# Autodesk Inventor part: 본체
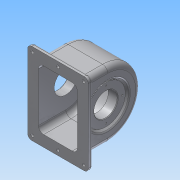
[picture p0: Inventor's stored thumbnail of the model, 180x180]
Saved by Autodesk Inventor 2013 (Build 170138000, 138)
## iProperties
Created: 2015-09
Part Number: 본체
Material: 알루미늄 6061
Document SubType Name: Modeling
Designer: user-11
Density: 2.71 g/cm^3
Mass: 756.275 g
Surface Area: 900.347 cm^2
Volume: 279.068 cm^3
Author: user-11
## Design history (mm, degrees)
sketch "스케치2"
  geometry: L1 (-52, 7)-(52, 7); L2 (52, 7)-(52, 0); L3 (52, 0)-(-52, 0); L4 (-52, 0)-(-52, 7); 1 further point
  constraints: 8 end point, 2 parallel, 1 horizontal, 1 perpendicular
  dimensions: "d0" = 7 distance from line of point (0, 0) L1; "d1" = 0 distance from line of point (0, 0) L3; "d2" = 52 distance from line of point (0, 0) L4; "d3" = 104 distance between parallel lines of L4 L2
extrude "돌출1" new body sketch "스케치2" stored distance "d4" = 140; taper "d5" = 0 deg
node "작업 평면1"
sketch "스케치3"
  geometry: L1 (0, 0)-(140, 0) reference; L2 (0, 7)-(0, 0) reference; L3 (140, 7)-(0, 7) reference; L4 (140, 0)-(140, 7) reference; L5 (70, 0)-(70, 110); L6 (70, 104)-(79.701, 104); L7 (70, 47)-(96.584, 47); L8 (13, 47)-(13, 7); L9 (127, 47)-(127, 7); A1 r 57 centre (70, 47) between (127, 47) and (13, 47)
  constraints: 10 end point, 5 point on line, 3 parallel, 3 point on circle, 2 perpendicular, 2 tangent, 1 centre point, 1 coincident
  dimensions: "d6" = 110 distance of L5.start L5.end; "d7" = 6 distance from line of L5.end L6; "d8" = 47 distance between parallel lines of L1 L7
extrude "돌출2" join sketch "스케치3" stored distance "d9" = 77; taper "d10" = 0 deg
node "작업 평면2"
sketch "스케치4"
  geometry: L1 (-127, 7)-(-127, 47) reference; L2 (-13, 47)-(-13, 7) reference; L3 (-121, 47)-(-121, 0); L4 (-19, 47)-(-19, 0); L5 (0, 0)-(-140, 0) reference; A1 r 57 centre (-70, 47) between (-13, 47) and (-127, 47) reference; A2 r 51 centre (-70, 47) between (-19, 47) and (-121, 47); 1 further point
  constraints: 4 end point, 3 parallel, 2 point on circle, 2 point on line, 1 centre point, 1 coincident, 1 tangent
  dimensions: "d11" = 51 distance from line of point (-70, 0) L3; "d12" = 102 distance between parallel lines of L3 L4
extrude "돌출3" cut sketch "스케치4" stored distance "d13" = 67; taper "d14" = 0 deg
node "작업 평면3"
sketch "스케치5"
  geometry: L1 (-38.5, 104)-(-38.5, 47) reference; L2 (-38.5, 47)-(-38.5, 7) reference; L3 (-33.5, 47)-(-33.5, 0) reference; L4 (-33.5, 98)-(-33.5, 47) reference; L5 (33.5, 47)-(33.5, 98) reference; L6 (33.5, 0)-(33.5, 47) reference; L7 (38.5, 7)-(38.5, 47) reference; L8 (38.5, 47)-(38.5, 104) reference; L9 (-49.023, 47)-(65.763, 47); L10 (-19.5, 67)-(-19.5, 75); L11 (-19.5, 75)-(-33.5, 86.747); L12 (-19.5, 67)-(-33.5, 67); L13 (48.5, 47)-(48.5, 78); L14 (48.5, 78)-(38.5, 78); L15 (48.5, 47)-(38.5, 47); 1 further point
  constraints: 14 end point, 5 perpendicular, 4 point on line
  dimensions: "d15" = 47 distance from line of point (0, 0) L9; "d16" = 40 diameter of L12 L9; "d17" = 56 diameter of L10.end L9; "d18" = 50 deg angle of L4 L11; "d19" = 10 distance between parallel lines of L8 L13; "d20" = 62 diameter of L14 L9; "d21" = 19 distance between parallel lines of L1 L10
revolve "회전1" sketch "스케치5" stored, may be unused: angle "d22" = 90 deg
sketch "스케치6"
  geometry: C1 r 31 at (0, 0) reference; C2 r 20 at (0, 0); 1 further point
  constraints: 1 centre point, 1 coincident
  dimensions: "d23" = 40 diameter of C2
extrude "돌출4" cut sketch "스케치6" stored distance "d25" = 67; taper "d26" = 0 deg
sketch "스케치7"
  geometry: L1 (-33.5, 86.747)-(-19.5, 75) reference; L2 (-33.5, 7.253)-(-19.5, 19) reference; L3 (-35.5, 80)-(-35.5, 67); L4 (-19.5, 27)-(-19.5, 67) reference; L5 (-38.5, 84.416)-(-33.237, 80); L6 (-19.5, 19)-(-19.5, 75) reference; L7 (-38.5, 104)-(-38.5, 47) reference; L8 (-38.5, 27)-(-38.5, 67) reference; L9 (-38.5, 47)-(-38.5, 7) reference; L10 (-66.176, 47)-(7.982, 47); L11 (33.5, 0)-(-33.5, 0) reference; L12 (-35.5, 80)-(-33.237, 80); L13 (-19.5, 67)-(-38.5, 67) reference; 1 further point
  constraints: 8 end point, 2 parallel, 2 point on line, 1 perpendicular, 1 vertical
  dimensions: "d27" = 16 distance between parallel lines of L4 L3; "d28" = 5 distance between parallel lines of L1 L5; "d29" = 47 distance between parallel lines of L11 L10; "d30" = 66 diameter of L3.start L10
revolve "회전2" sketch "스케치7" stored, may be unused: angle "d31" = 90 deg
sketch "스케치8"
  geometry: C1 r 20 at (0, 0) reference; C2 r 28 at (0, 0); C3 r 5.258 at (0, 28); 1 further point
  constraints: 2 centre point, 1 coincident
  dimensions: "d32" = 56 diameter of C2
hole "구멍1" sketch "스케치8" at (0, 28) diameter "d34" = 2.459; stored, may be unused: countersink angle "d38" = 90 deg, drill point angle "d40" = 118 deg; dims "d35" = 7, "d36" = 4, "d37" = 2, "d39" = 9
sketch "스케치9" dims "d44" = 48
  geometry: C1 r 31 at (0, 0) reference; C2 r 2.394 at (0, 24); 2 further points
  constraints: 1 centre point, 1 coincident, 1 vertical alignment, 2 other
hole "구멍2" sketch "스케치9" at (0, 24) diameter "d46" = 2.459; stored, may be unused: countersink angle "d50" = 90 deg, drill point angle "d52" = 118 deg; dims "d47" = 6, "d48" = 4, "d49" = 2, "d51" = 8
node "작업 평면4"
sketch "스케치10"
  geometry: L1 (0, 0)-(0, 110); L2 (38.5, 104)-(-38.5, 104) reference; L3 (-33.5, 98)-(33.5, 98) reference; L4 (0, 110)-(-6, 110); L5 (-6, 110)-(-7.886, 99.307); L6 (-7.886, 99.307)-(0, 99.307)
  constraints: 8 end point, 1 parallel, 1 perpendicular, 1 point on line, 1 vertical
  dimensions: "d62" = 110 distance of L1.start L1.end; "d63" = 12 diameter of L4.end L1; "d64" = 100 deg angle of L6 L5
revolve "회전3" sketch "스케치10" stored, may be unused: angle "d65" = 90 deg
sketch "스케치11"
  geometry: C1 r 6 at (0, 0) reference
hole "구멍3" sketch "스케치11" at (0, 0) diameter "d66" = 4.134; stored, may be unused: countersink angle "d70" = 90 deg, drill point angle "d72" = 118 deg; dims "d67" = 15, "d68" = 4, "d69" = 2, "d71" = 8
sketch "스케치12"
  geometry: L1 (77, 0)-(77, -40) reference; L2 (38.5, -47)-(38.5, 77.946); L3 (28.206, -17)-(38.5, -17); L4 (-13.5, -47)-(90.5, -47) reference; L5 (13.613, -13.398)-(63.387, -13.398); L6 (63.387, -13.398)-(63.387, -20.602); L7 (63.387, -20.602)-(13.613, -20.602); L8 (13.613, -20.602)-(13.613, -13.398); L9 (13.613, -13.398)-(63.387, -20.602); L10 (63.387, -13.398)-(13.613, -20.602); L11 (38.5, -17)-(38.604, -21.845)
  constraints: 10 end point, 1 midpoint, 1 parallel, 1 perpendicular, 1 point on line, 2 other
  dimensions: "d73" = 30 distance between parallel lines of L4 L3; "d74" = 0 distance of L3.end L11.start; "d75" = 0 distance of L3.end L11.start
extrude "돌출5" join sketch "스케치12" distance "d76" = 0.5; taper "d77" = 0 deg
fillet "모깎기1" dims "d78" = 9
fillet "모깎기2" dims "d79" = 3
fillet "모깎기3" dims "d80" = 0.5
fillet "모깎기4" dims "d81" = 3
fillet "모깎기5" dims "d82" = 3
fillet "모깎기6" dims "d83" = 1
fillet "모깎기7" dims "d84" = 7
sketch "스케치13"
  geometry: L1 (97, -133)-(97, -7) reference; L2 (0, 0)-(90, 0) reference; L3 (-7, -7)-(-7, -133) reference; L4 (90, -140)-(0, -140) reference; L5 (74.5, -12)-(15.5, -12) reference; L6 (1, 9.606)-(1, -153.708); L7 (-16.915, -8)-(110.248, -8); L8 (89, 4.478)-(89, -155.246); L9 (-20.761, -132)-(107.428, -132); L10 (45, -70)-(45, 24.075); L11 (45, -70)-(45, -183.978); C1 r 2.5 at (1, -8); C2 r 2.5 at (89, -8); C3 r 2.5 at (89, -132); C4 r 2.5 at (1, -132); C5 r 2.5 at (45, -132); C6 r 2.5 at (45, -8)
  constraints: 12 end point, 12 point on line, 6 centre point, 5 perpendicular, 1 collinear
  dimensions: "d85" = 8 distance between parallel lines of L3 L6; "d87" = 8 distance between parallel lines of L2 L7; "d88" = 8 distance between parallel lines of L4 L9; "d89" = 8 distance between parallel lines of L1 L8; "d90" = 5 diameter of C4; "d91" = 5 diameter of C5; "d92" = 5 diameter of C3; "d93" = 5 diameter of C1; "d94" = 5 diameter of C2; "d95" = 5 diameter of C6
extrude "돌출6" cut sketch "스케치13" stored distance "d96" = 0.5; taper "d97" = 0 deg
fillet "모깎기8" dims "d98" = 3
chamfer "모따기1" distance "d99" = 1; stored, may be unused: second distance "d100" = 2, angle "d101" = 45 deg
chamfer "모따기2" distance "d102" = 1; stored, may be unused: second distance "d103" = 2, angle "d104" = 45 deg
node "솔리드1"
pattern_circular "원형 패턴1" dims angle "d42" = 360 deg
pattern_circular "원형 패턴2" dims angle "d54" = 360 deg
node "투영된 루프1"
